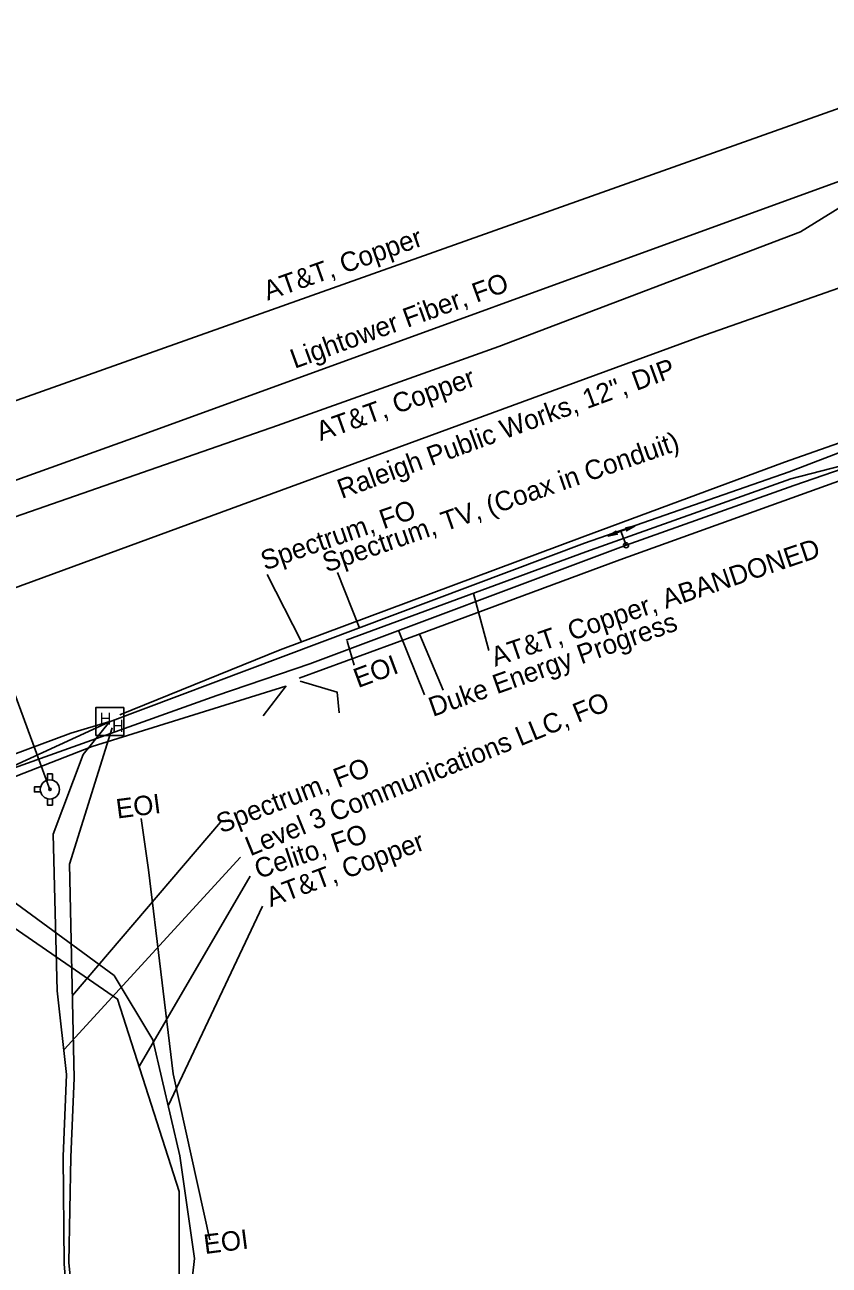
# Model space of a CAD drawing. Extents: x 2070721 to 2083039, y 729290 to 737883.
# Drawn here: x 2080763.5 to 2080929.2, y 734501.5 to 734756.8 of the extents above; entities that cross this region are included whole.
import ezdxf

# ---------------------------------------------------------------- set-up
doc = ezdxf.new("R2010")
doc.units = 0
for name, color, linetype in [('COGO Default Point Number', 7, 'Continuous'), ('Exist Utilities Gas UG Line SUE Cogo Point CELL', 7, 'Continuous'), ('Exist Utilities Gas UG Line SUE LOS B Cogo Comment', 7, 'Continuous'), ('Exist Utilities Gas UG Line SUE LOS B Cogo Number', 7, 'Continuous'), ('Exist Utilities Gas UG Line SUE LOS B Cogo Point CELL', 7, 'Continuous'), ('Exist Utilities Gas Valve CELL', 7, 'Continuous'), ('Exist Utilities Gas Valve Cogo Elevation', 7, 'Continuous'), ('Exist Utilities Other Unknown UG SUE Cogo Point CELL', 7, 'Continuous'), ('Exist Utilities Other Unknown UG SUE LOS B Cogo Comment', 7, 'Continuous'), ('Exist Utilities Other Unknown UG SUE LOS B Cogo Elevation', 7, 'Continuous'), ('Exist Utilities Other Unknown UG SUE LOS B Cogo Number', 7, 'Continuous'), ('Exist Utilities Other Unknown UG SUE LOS B Cogo Point CELL', 7, 'Continuous'), ('Exist Utilities Power Pole CELL', 7, 'Continuous'), ('Exist Utilities Power Pole Cogo Elevation', 7, 'Continuous'), ('Exist Utilities Power UG Cable Cogo Point CELL', 7, 'Continuous'), ('Exist Utilities Telephone UG Cable Cogo Point CELL', 7, 'Continuous'), ('Exist Utilities Telephone UG Cable SUE LOS C Cogo Comment', 7, 'Continuous'), ('Exist Utilities TV Pedestal CELL', 7, 'Continuous'), ('Exist Utilities TV Pedestal Cogo Elevation', 7, 'Continuous'), ('Exist Utilities TV UG Cable Cogo Point CELL', 7, 'Continuous'), ('Exist Utilities TV UG Cable SUE LOS C Cogo Comment', 7, 'Continuous'), ('Exist Utilities TV UG Cable SUE LOS C Cogo Number', 7, 'Continuous'), ('Exist Utilities TV UG Cable SUE LOS C Cogo Point CELL', 7, 'Continuous'), ('Exist Utilities Water Manhole Cogo Elevation', 7, 'Continuous'), ('Exist Utilities Water Manhole Cogo Number', 7, 'Continuous'), ('Exist Utilities Water Meter CELL', 7, 'Continuous'), ('Exist Utilities Water Meter Cogo Number', 7, 'Continuous'), ('Exist Utilities Water UG Line SUE LOS B Cogo Comment', 7, 'Continuous'), ('Exist Utilities Water UG Line SUE LOS B Cogo Elevation', 7, 'Continuous'), ('Exist Utilities Water UG Line SUE LOS B Cogo Number', 7, 'Continuous')]:
    doc.layers.add(name, color=color, linetype=linetype)

msp = doc.modelspace()

# ---------------------------------------------------------------- linework, layer by layer
at = {"layer": 'COGO Default Point Number'}
msp.add_line((2080768.66, 734599.39), (2080768.66, 734599.39), dxfattribs=at)
for points in [[(2080768.15, 734601.31), (2080768.15, 734602.59), (2080769.17, 734602.59), (2080769.17, 734601.28)], [(2080766.75, 734599.91), (2080765.46, 734599.91), (2080765.46, 734598.88), (2080766.75, 734598.88)], [(2080768.15, 734597.48), (2080768.15, 734596.19), (2080769.17, 734596.19), (2080769.17, 734597.51)]]:
    msp.add_lwpolyline(points, dxfattribs=at)
for radius in [1.98, 0.243]:
    msp.add_circle((2080768.66, 734599.39), radius, dxfattribs=at)
at = {"layer": 'Exist Utilities Gas UG Line SUE LOS B Cogo Number'}
msp.add_line((2080773.28, 734556.99), (2080803.81, 734592.63), dxfattribs=at)
at = {"layer": 'Exist Utilities Gas Valve CELL'}
for p, q in [((2080840.5, 734631.96), (2080845.82, 734618.86)), ((2080844.88, 734631.24), (2080849.68, 734619.84))]:
    msp.add_line(p, q, dxfattribs=at)
at = {"layer": 'Exist Utilities Gas Valve Cogo Elevation'}
for p, q in [((2080855.94, 734639.74), (2080859.08, 734628.02)), ((2080793.04, 734534.25), (2080812.48, 734575.36))]:
    msp.add_line(p, q, dxfattribs=at)
at = {"layer": 'Exist Utilities Other Unknown UG SUE Cogo Point CELL'}
msp.add_line((2080832.35, 734632.82), (2080827.87, 734644.08), dxfattribs=at)
at = {"layer": 'Exist Utilities Other Unknown UG SUE LOS B Cogo Comment'}
msp.add_line((2080787.04, 734542.33), (2080809.94, 734581.56), dxfattribs=at)
at = {"layer": 'Exist Utilities Other Unknown UG SUE LOS B Cogo Number'}
msp.add_line((2080829.88, 734629.94), (2080831.35, 734624.97), dxfattribs=at)
at = {"layer": 'Exist Utilities Power Pole CELL'}
msp.add_lwpolyline([(2080232.24, 734245.67), (2080237.5, 734254.36), (2080238.66, 734282.35), (2080245.75, 734323.83), (2080258.86, 734369.55), (2080269.86, 734398.57), (2080309.08, 734449.32), (2080323.63, 734464.88), (2080355.41, 734492.16), (2080379.52, 734509.8), (2080416.03, 734529.49), (2080502.71, 734562.3), (2080573.96, 734587.12), (2080616.57, 734603.22), (2080677.16, 734624.99), (2080749, 734651.22), (2080815.57, 734674.3), (2080861.11, 734690.56), (2080923.26, 734714.15), (2080934.26, 734720.97)], dxfattribs=at)
at = {"layer": 'Exist Utilities Power Pole Cogo Elevation'}
msp.add_lwpolyline([(2080667.78, 734563.47), (2080684.69, 734572.51), (2080703.86, 734583.33), (2080803.07, 734618.73), (2080822.19, 734625.25), (2080887.34, 734649.65)], dxfattribs=at)
at = {"layer": 'Exist Utilities Power UG Cable Cogo Point CELL'}
for p, q in [((2080889.19, 734653.64), (2080883.61, 734651.54)), ((2080886.25, 734652.54), (2080889.19, 734653.64)), ((2080887.34, 734649.65), (2080886.25, 734652.54)), ((2080887.34, 734649.65), (2080887.34, 734649.65))]:
    msp.add_line(p, q, dxfattribs=at)
for points in [[(2080883.61, 734651.54), (2080885.33, 734652.56), (2080885.06, 734652.09), (2080885.52, 734651.94)], [(2080889.19, 734653.64), (2080887.46, 734652.62), (2080887.74, 734653.09), (2080887.27, 734653.24)]]:
    msp.add_lwpolyline(points, close=True, dxfattribs=at)
msp.add_circle((2080887.34, 734649.65), 0.517, dxfattribs=at)
at = {"layer": 'Exist Utilities Telephone UG Cable Cogo Point CELL'}
msp.add_line((2080780.99, 734613.36), (2080780.99, 734613.36), dxfattribs=at)
msp.add_lwpolyline([(2080778.11, 734610.48), (2080783.86, 734610.48), (2080783.86, 734616.23), (2080778.11, 734616.23), (2080778.11, 734610.48)], dxfattribs=at)
at = {"layer": 'Exist Utilities Telephone UG Cable SUE LOS C Cogo Comment'}
msp.add_lwpolyline([(2080787.43, 734593.43), (2080789, 734582.82), (2080794.08, 734540.84), (2080801.61, 734506.7)], dxfattribs=at)
at = {"layer": 'Exist Utilities TV Pedestal CELL'}
for points in [[(2080783.05, 734614.76), (2080816.08, 734628.1), (2080878.27, 734651.3), (2080919.99, 734666.74), (2080989.43, 734691.22), (2081068.18, 734719.46), (2081106.14, 734736.11), (2081119.77, 734739.04)], [(2080792.49, 734446.91), (2080784.46, 734449.31), (2080777.2, 734454.29), (2080772.59, 734502.03), (2080772.98, 734523.68), (2080773.64, 734539.98), (2080772.68, 734584.01), (2080781.47, 734612.06)]]:
    msp.add_lwpolyline(points, dxfattribs=at)
at = {"layer": 'Exist Utilities TV Pedestal Cogo Elevation'}
for points in [[(2080357.06, 734003.27), (2080353.32, 734006.79), (2080296.63, 734072.2), (2080261.95, 734141.13), (2080251.22, 734185.42), (2080250, 734189.2), (2080244.12, 734248.6), (2080244.13, 734251.5), (2080244.63, 734259.68), (2080245.13, 734264.1), (2080254.44, 734320.44), (2080276.53, 734380.91), (2080391.41, 734503.18), (2080497.9, 734548.7), (2080500.72, 734549.83), (2080585.45, 734578.7), (2080702.53, 734619.89), (2080710.17, 734622.62), (2080743.51, 734634.52), (2080754.26, 734638.28), (2080902.52, 734692.58), (2081024.44, 734735.33)], [(2080754.33, 734638.34), (2080755.39, 734635.25), (2080768.66, 734599.39)]]:
    msp.add_lwpolyline(points, dxfattribs=at)
at = {"layer": 'Exist Utilities TV UG Cable Cogo Point CELL'}
for points in [[(2080527.18, 734594.58), (2080756.63, 734677.7), (2080975.53, 734755.33), (2081114.85, 734806.49), (2081251.31, 734880.3), (2081357.91, 734934.96), (2081407.46, 734955.63), (2081557.34, 735013.56), (2081611.19, 735031.21), (2081670.8, 735036.79), (2081727.82, 735033.26), (2081796.62, 735020.83), (2081876.61, 734998.57), (2081913.61, 734982.12), (2081940.08, 734960.79), (2081955.36, 734908.6), (2081940.34, 734844.38), (2081917.15, 734795.51)], [(2080829.69, 734630.12), (2080879.03, 734648.33), (2080921.3, 734663.31), (2080935.93, 734667.09), (2080939.07, 734669.34), (2080979.29, 734683.22), (2081029.96, 734701.46), (2081063.22, 734714.57)], [(2080392.43, 734459.45), (2080392.18, 734455.98), (2080369.79, 734491.21), (2080371.64, 734506.16), (2080398.8, 734522.93), (2080423.1, 734536.76), (2080488.87, 734560.43), (2080551.19, 734581.93), (2080605.97, 734600.8), (2080683.17, 734629.37), (2080713.38, 734633.09), (2080745.42, 734609.78), (2080760.77, 734576.63), (2080781.91, 734561.06), (2080789.84, 734547.84), (2080795.45, 734523.96), (2080798.47, 734502.81), (2080795.45, 734476.11), (2080787.39, 734456.13)]]:
    msp.add_lwpolyline(points, dxfattribs=at)
at = {"layer": 'Exist Utilities TV UG Cable SUE LOS C Cogo Comment'}
msp.add_line((2080817.31, 734620.69), (2080812.59, 734614.55), dxfattribs=at)
for points in [[(2080820, 734622.29), (2080844.38, 734631.25), (2080886.06, 734646.68), (2080939.66, 734665.94), (2080971.55, 734676.3), (2081034.15, 734699.4), (2081093.26, 734724.52), (2081121.49, 734735.79), (2081125.29, 734737.91), (2081128.97, 734740.08), (2081128.97, 734740.08)], [(2080887.34, 734649.65), (2080921.88, 734661.96), (2080962.1, 734675.79), (2081000.33, 734689.04), (2081037.16, 734702.37)], [(2080820.22, 734621.7), (2080827.8, 734619.42), (2080828.24, 734615.15)], [(2080667.78, 734563.47), (2080675.81, 734558.73), (2080709.93, 734583.03), (2080741.96, 734594.47), (2080777.33, 734608.24), (2080817.29, 734620.64)]]:
    msp.add_lwpolyline(points, dxfattribs=at)
at = {"layer": 'Exist Utilities TV UG Cable SUE LOS C Cogo Number'}
msp.add_lwpolyline([(2080540.63, 734520.42), (2080564.59, 734528.02), (2080616.67, 734550.17), (2080656.9, 734568.75), (2080683.34, 734575.14), (2080742.18, 734595.53), (2080780.96, 734613.32), (2080816.71, 734626.79), (2080878.8, 734650.08), (2080920.95, 734664.77), (2080961.27, 734680.22)], dxfattribs=at)
at = {"layer": 'Exist Utilities TV UG Cable SUE LOS C Cogo Point CELL'}
for points in [[(2080717.24, 734648.01), (2080746.66, 734657.69), (2080787.43, 734672.3), (2080932.78, 734725.13), (2080966.26, 734736.59)], [(2080792.52, 734446.86), (2080775.46, 734454.16), (2080771.57, 734501.71), (2080771.41, 734523.8), (2080772.11, 734540.7), (2080770.17, 734557.91), (2080769.35, 734590.18), (2080775.5, 734606.58), (2080780.96, 734613.32)]]:
    msp.add_lwpolyline(points, dxfattribs=at)
at = {"layer": 'Exist Utilities Water Manhole Cogo Elevation'}
for p, q in [((2080820.47, 734629.78), (2080813.43, 734643.61)), ((2080771.63, 734545.84), (2080807.94, 734585.43))]:
    msp.add_line(p, q, dxfattribs=at)
at = {"layer": 'Exist Utilities Water UG Line SUE LOS B Cogo Elevation'}
msp.add_lwpolyline([(2080615.4, 734550.71), (2080655.3, 734569.86), (2080692.31, 734580.99), (2080772.95, 734610.98), (2080780.99, 734613.36)], dxfattribs=at)
at = {"layer": 'Exist Utilities Water UG Line SUE LOS B Cogo Number'}
msp.add_lwpolyline([(2080652.77, 734625.25), (2080667.42, 734617.06), (2080717.34, 734601.19), (2080782.55, 734556.25), (2080795.25, 734516.63), (2080795.25, 734490.1), (2080786.86, 734462.06), (2080786.86, 734458.84)], dxfattribs=at)

# ---------------------------------------------------------------- texts
at = {"layer": 'Exist Utilities Gas UG Line SUE Cogo Point CELL'}
msp.add_text('Raleigh Public Works, 12", DIP', height=4, rotation=20.1152, dxfattribs=at).set_placement((2080828.76, 734659.18))
at = {"layer": 'Exist Utilities Gas UG Line SUE LOS B Cogo Comment'}
for s, rotation, p in [('Lightower Fiber, FO', 19.9746, (2080819.07, 734685.97)), ('Spectrum, FO ', 19.1427, (2080812.94, 734644.45)), ('Level 3 Communications LLC, FO', 22.1458, (2080809.92, 734585.61))]:
    msp.add_text(s, height=4, rotation=rotation, dxfattribs=at).set_placement(p)
at = {"layer": 'Exist Utilities Gas UG Line SUE LOS B Cogo Point CELL'}
msp.add_text(' Spectrum, FO', height=4, rotation=21.2063, dxfattribs=at).set_placement((2080802.52, 734589.77))
at = {"layer": 'Exist Utilities Other Unknown UG SUE LOS B Cogo Elevation'}
msp.add_text('Celito, FO ', height=4, rotation=18.657, dxfattribs=at).set_placement((2080811.61, 734580.95))
at = {"layer": 'Exist Utilities Other Unknown UG SUE LOS B Cogo Point CELL'}
msp.add_text('EOI', height=4, rotation=20.4341, dxfattribs=at).set_placement((2080832.13, 734620.24))
at = {"layer": 'Exist Utilities Telephone UG Cable Cogo Point CELL'}
for p in [(2080778.9, 734612.71), (2080781.47, 734611.25)]:
    msp.add_text('H', height=2.5, dxfattribs=at).set_placement(p)
at = {"layer": 'Exist Utilities Water Manhole Cogo Number'}
msp.add_text('Spectrum, TV, (Coax in Conduit)', height=4, rotation=19.1427, dxfattribs=at).set_placement((2080825.64, 734644.03))
at = {"layer": 'Exist Utilities Water Meter CELL'}
msp.add_text('Duke Energy Progress', height=4, rotation=19.4936, dxfattribs=at).set_placement((2080847.54, 734614.31))
at = {"layer": 'Exist Utilities Water Meter Cogo Number'}
for s, rotation, p in [('AT&T, Copper', 19.5258, (2080813.52, 734700)), ('AT&T, Copper', 19.649, (2080824.39, 734671.08)), ('AT&T, Copper, ABANDONED', 18.6897, (2080860.36, 734624.63)), ('AT&T, Copper', 20.4865, (2080814.12, 734575.14))]:
    msp.add_text(s, height=4, rotation=rotation, dxfattribs=at).set_placement(p)
at = {"layer": 'Exist Utilities Water UG Line SUE LOS B Cogo Comment'}
for p in [(2080782.55, 734593.39), (2080800.6, 734503.74)]:
    msp.add_text('EOI', height=4, rotation=7.3783, dxfattribs=at).set_placement(p)

doc.saveas('drawing.dxf')
